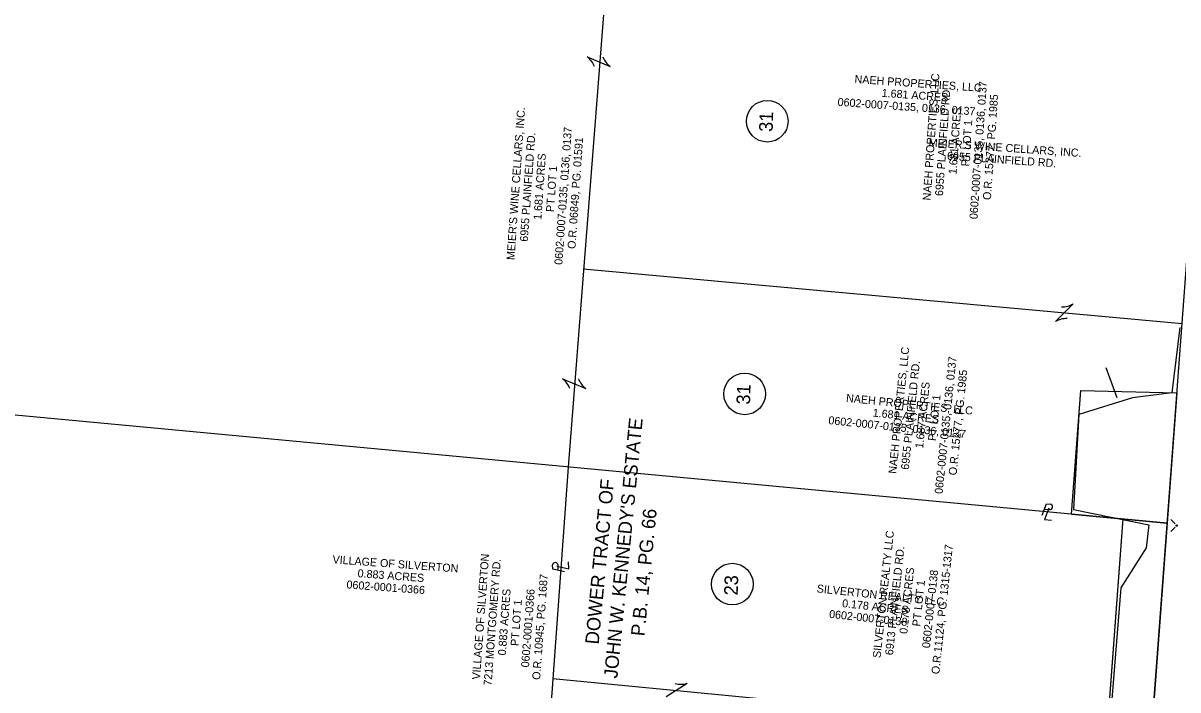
# Model space of a CAD drawing. Extents: x 204354 to 231038, y 361459 to 365260.
# Drawn here: x 220261.9 to 220550.5, y 362327.5 to 362494.1 of the extents above; entities that cross this region are included whole.
import ezdxf

# ---------------------------------------------------------------- set-up
doc = ezdxf.new("R2010")
doc.units = 0
for name, color, linetype in [('CM_Corridor_Point_Control', 7, 'Continuous'), ('DT_P_Contour_Minor', 7, 'Continuous'), ('DT_P_Contour_Text', 7, 'Continuous'), ('DT_P_Triangles', 7, 'Continuous'), ('DT_X_Contour_Minor', 7, 'Continuous'), ('MD_P_Intersection_MatchLine', 7, 'Continuous'), ('MD_P_Surface_Asphalt_Concrete_Base', 7, 'Continuous'), ('MD_P_SW_BOT', 7, 'Continuous'), ('PV_P_Walk', 7, 'Continuous'), ('SC_Shading1', 7, 'Continuous')]:
    doc.layers.add(name, color=color, linetype=linetype)

msp = doc.modelspace()

# ---------------------------------------------------------------- linework, layer by layer
at = {"layer": 'DT_P_Contour_Text'}
for centre in [(220447.88, 362469.56), (220442.23, 362401.46), (220439.15, 362353.93)]:
    msp.add_circle(centre, 5.2, dxfattribs=at)
at = {"layer": 'DT_P_Triangles'}
msp.add_lwpolyline([(220551, 362418.04), (220548.96, 362401.73), (220539.1, 362400.45), (220525.75, 362396.34), (220524.42, 362372.55), (220543.23, 362368.74), (220542.52, 362362.97), (220536.18, 362353), (220530.49, 362281.93)], dxfattribs=at)
at = {"layer": 'MD_P_Intersection_MatchLine'}
for p, q in [((220532.45, 362408.05), (220535.22, 362400.53)), ((220523.89, 362371.41), (220526.19, 362402.26)), ((220523.89, 362371.42), (220526.19, 362402.26)), ((220526.19, 362402.26), (220550.21, 362401.7)), ((220523.89, 362371.42), (220547.79, 362369.18)), ((220529.39, 362270.5), (220536.83, 362370.22)), ((220529.39, 362270.5), (220536.83, 362370.21))]:
    msp.add_line(p, q, dxfattribs=at)
at = {"layer": 'MD_P_Surface_Asphalt_Concrete_Base'}
for p, q in [((220548.68, 362370.08), (220549.77, 362368.98)), ((220548.68, 362367.06), (220549.77, 362368.15))]:
    msp.add_line(p, q, dxfattribs=at)
msp.add_circle((220550.19, 362368.57), 0.17, dxfattribs=at)
at = {"layer": 'MD_P_SW_BOT'}
for p, q in [((220409.9, 362533.9), (220398.1, 362383.18)), ((220402.88, 362485.61), (220408.66, 362483.24)), ((220405.77, 362484.42), (220405.77, 362484.42)), ((220401.9, 362432.66), (220551.51, 362419.04)), ((220519.89, 362419.51), (220524.31, 362423.93)), ((220522.1, 362421.72), (220522.1, 362421.72)), ((220547.79, 362369.18), (220129.61, 362408.29)), ((220396.73, 362405.2), (220402.51, 362402.84)), ((220399.62, 362404.02), (220399.62, 362404.02)), ((220398.11, 362383.18), (220392.82, 362310.29)), ((220517.12, 362372.68), (220518.41, 362372.56)), ((220517.86, 362371.98), (220517.86, 362371.98)), ((220395.65, 362357.37), (220395.61, 362358.67)), ((220396.25, 362358.19), (220396.25, 362358.19)), ((220394.27, 362330.37), (220543.82, 362315.97)), ((220422.58, 362325.89), (220427.9, 362329.17)), ((220425.24, 362327.53), (220425.24, 362327.53))]:
    msp.add_line(p, q, dxfattribs=at)
for points in [[(220516.55, 362371.13), (220517.61, 362374.01), (220518.64, 362373.91)], [(220518.21, 362372.91), (220517.15, 362370.04), (220518.89, 362369.88)], [(220397.25, 362357), (220394.27, 362357.69), (220394.24, 362358.72)], [(220395.28, 362358.43), (220398.26, 362357.72), (220398.21, 362359.47)]]:
    msp.add_lwpolyline(points, dxfattribs=at)
for centre, radius, start, end in [((220399.73, 362481.3), 5.34, 21.2337, 53.8762), ((220411.81, 362487.55), 5.34, 201.2337, 233.8762), ((220521.55, 362428.5), 5.34, 268.4961, 301.1387), ((220522.65, 362414.94), 5.34, 88.4961, 121.1387), ((220393.58, 362400.89), 5.34, 21.2337, 53.8762), ((220405.66, 362407.15), 5.34, 201.2337, 233.8762), ((220518.47, 362373.24), 0.69, 265.1289, 75.986), ((220394.92, 362358.64), 0.69, 2.1187, 172.9759), ((220426.27, 362334.25), 5.34, 255.1519, 287.7944)]:
    msp.add_arc(centre, radius, start, end, dxfattribs=at)
at = {"layer": 'PV_P_Walk'}
msp.add_line((220534.47, 362190.67), (220633.24, 363514.5), dxfattribs=at)
at = {"layer": 'SC_Shading1'}
for points in [[(220547.79, 362369.18), (220523.89, 362371.42), (220526.19, 362402.26), (220550.21, 362401.7)], [(220540.35, 362269.47), (220529.39, 362270.5), (220536.83, 362370.21), (220547.79, 362369.18)]]:
    msp.add_lwpolyline(points, close=True, dxfattribs=at)

# ---------------------------------------------------------------- texts
at = {"layer": 'CM_Corridor_Point_Control'}
for s, p in [("MEIER'S WINE CELLARS, INC.", (220488.16, 362463.29)), ('6955 PLAINFIELD RD.', (220492.74, 362459.96))]:
    msp.add_text(s, height=2, rotation=356, dxfattribs=at).set_placement(p)
at = {"layer": 'DT_P_Contour_Minor'}
for s, height, rotation, p in [('NAEH PROPERTIES, LLC', 2, 86, (220488.69, 362449.72)), ('0602-0007-0135, 0136, 0137', 2, 86, (220500.39, 362445.06)), ('6955 PLAINFIELD RD.', 2, 86, (220491.77, 362450.82)), ('O.R. 15277, PG. 1985', 2, 86, (220503.73, 362449.83)), ("MEIER'S WINE CELLARS, INC.", 2, 86, (220384.71, 362434.83)), (' 1.681 ACRES', 2, 86, (220495.11, 362455.53)), ('0602-0007-0135, 0136, 0137', 2, 86, (220396.66, 362433.65)), ('PT LOT 1', 2, 86, (220498.3, 362458.23)), ('6955 PLAINFIELD RD.', 2, 86, (220388.04, 362439.41)), ('O.R. 06849, PG. 01591', 2, 86, (220399.94, 362437.61)), (' 1.681 ACRES', 2, 86, (220391.37, 362444.12)), ('PT LOT 1', 2, 86, (220394.57, 362446.82)), ('NAEH PROPERTIES, LLC', 2, 84.123, (220480.12, 362381.43)), ('6955 PLAINFIELD RD.', 2, 84.123, (220483.24, 362382.43)), ('0602-0007-0135, 0136, 0137', 2, 84.123, (220491.66, 362376.39)), ('O.R. 15277, PG. 1985', 2, 84.123, (220495.16, 362381.05)), (' 1.687 ACRES', 2, 84.123, (220486.73, 362387.03)), ('PT LOT 1', 2, 84.123, (220490.01, 362389.62)), ("JOHN W. KENNEDY'S ESTATE", 3.4, 84.4086, (220410.42, 362330.31)), ('DOWER TRACT OF', 3.4, 84.5785, (220405.74, 362338.78)), ('14, PG. 66', 3.4, 84.4086, (220418.17, 362350.98)), ('SILVERTON REALTY LLC', 2, 83.953, (220476.19, 362335.41)), ('6913 PLAINFIELD RD.', 2, 83.953, (220479.28, 362336.11)), ('O.R.11124, PG. 1315-1317', 2, 83.953, (220490.85, 362331.36)), ('VILLAGE OF SILVERTON', 2, 85.7857, (220376.09, 362330.03)), ('7213 MONTGOMERY RD.', 2, 85.7857, (220378.98, 362328.51)), (' 0.178 ACRES', 2, 83.953, (220482.78, 362340.7)), ('0602-0007-0138', 2, 83.953, (220488.52, 362337.87)), ('O.R. 10945, PG. 1687', 2, 85.7857, (220391.12, 362329.97)), ('PT LOT 1', 2, 83.953, (220486.07, 362343.28)), ('0.883 ACRES', 2, 85.7857, (220382.55, 362336.08)), ('0602-0001-0366', 2, 85.7857, (220388.34, 362333.08)), ('PT LOT 1', 2, 85.7857, (220385.73, 362338.42)), ('P.B.', 3.4, 84.4086, (220417.18, 362340.83))]:
    msp.add_text(s, height=height, rotation=rotation, dxfattribs=at).set_placement(p)
at = {"layer": 'DT_P_Contour_Text'}
for s, p in [('31', (220449.22, 362466.86)), ('31', (220443.57, 362398.75)), ('23', (220440.49, 362351.07))]:
    msp.add_text(s, height=3.4, rotation=88.3143, dxfattribs=at).set_placement(p)
at = {"layer": 'DT_X_Contour_Minor'}
for s, rotation, p in [('NAEH PROPERTIES, LLC', 356, (220469.64, 362479.14)), (' 1.681 ACRES', 356, (220475.67, 362475.71)), ('0602-0007-0135, 0136, 0137', 356, (220465.4, 362473.42)), ('NAEH PROPERTIES, LLC', 354.123, (220467.5, 362399.5)), (' 1.681 ACRES', 354.123, (220473.41, 362395.88)), ('0602-0007-0135, 0136, 0137', 354.123, (220463.08, 362393.92)), ('VILLAGE OF SILVERTON', 355.7857, (220339.2, 362359.15)), ('0.883 ACRES', 355.7857, (220345.47, 362355.68)), ('0602-0001-0366', 355.7857, (220342.69, 362352.88)), ('SILVERTON REALTY LLC', 353.953, (220460.17, 362351.89)), (' 0.178 ACRES', 353.953, (220465.77, 362348.28)), ('0602-0007-0138', 353.953, (220463.25, 362345.53))]:
    msp.add_text(s, height=2, rotation=rotation, dxfattribs=at).set_placement(p)

doc.saveas('drawing.dxf')
